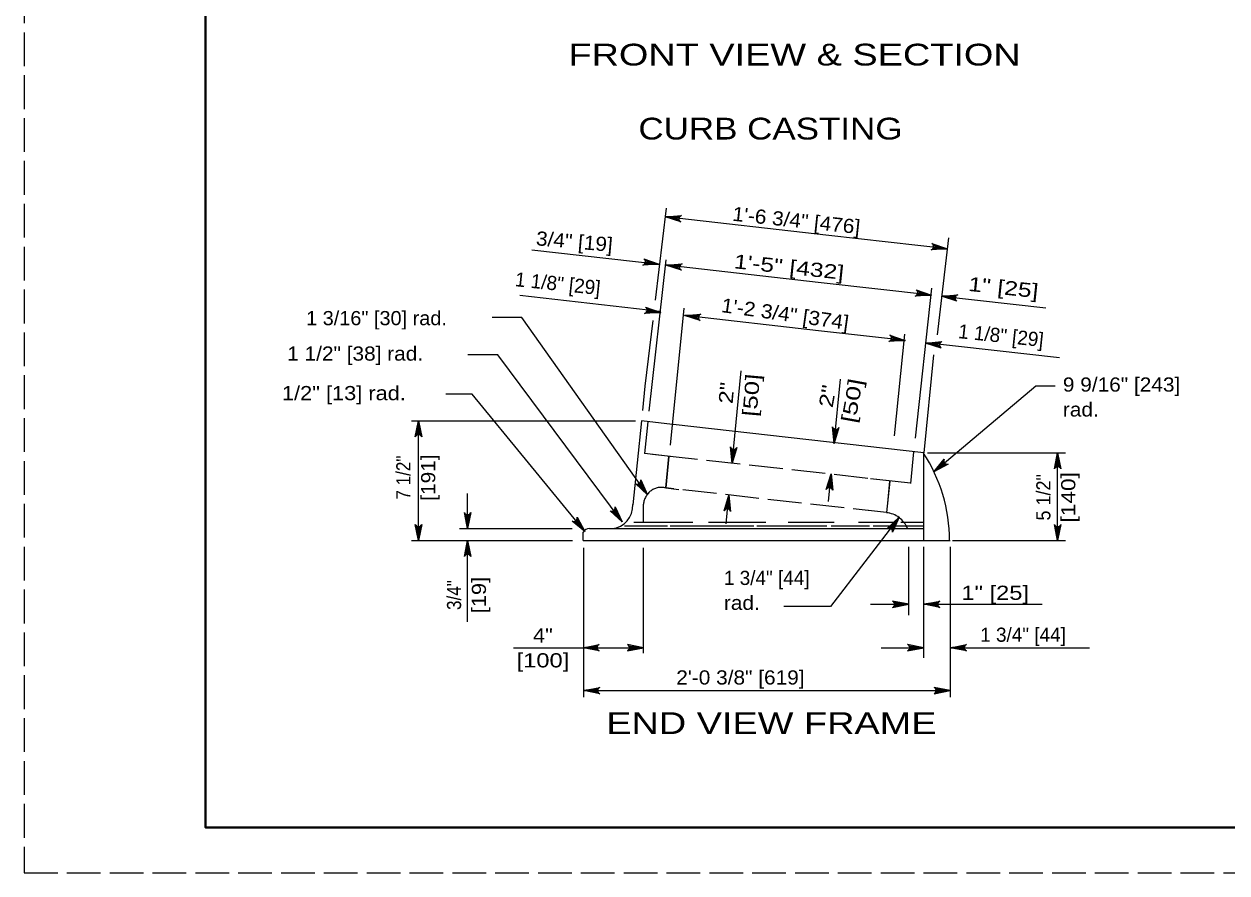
# Model space of a CAD drawing. Extents: x 1352.5 to 1386.5, y 735.9 to 779.9.
# Drawn here: x 1352.51 to 1365.77, y 735.92 to 745.27 of the extents above; entities that cross this region are included whole.
import ezdxf
from ezdxf.enums import TextEntityAlignment as Align

# ---------------------------------------------------------------- set-up
doc = ezdxf.new("R2010")
doc.units = 0
doc.header["$LTSCALE"] = 0.062
doc.linetypes.add('LONG_DASHED', pattern=[7.5, 6, -1.5])
doc.layers.add('1', color=7, linetype='Continuous', lineweight=13)

msp = doc.modelspace()

# ---------------------------------------------------------------- linework, layer by layer
at = {"layer": '1'}
for p, q in [((1359.587, 743.23908), (1359.467, 742.22625)), ((1359.73892, 743.14742), (1359.57708, 743.14308)), ((1361.38233, 742.93892), (1359.57708, 743.14308)), ((1359.72942, 743.12592), (1359.57708, 743.14308)), ((1359.73058, 743.11125), (1359.57708, 743.14308)), ((1359.7355, 743.10025), (1359.57708, 743.14308)), ((1359.73233, 743.13692), (1359.57708, 743.14308)), ((1362.68767, 742.79175), (1361.38233, 742.93908)), ((1362.53067, 742.83942), (1362.68767, 742.79175)), ((1362.53525, 742.82825), (1362.68767, 742.79175)), ((1362.70017, 742.91475), (1362.5735, 741.84375)), ((1359.51, 742.62008), (1358.11, 742.77825)), ((1362.52583, 742.79242), (1362.68767, 742.79175)), ((1362.53275, 742.80275), (1362.68767, 742.79175)), ((1362.536, 742.81358), (1362.68767, 742.79175)), ((1359.35008, 742.62375), (1359.51192, 742.62308)), ((1359.35492, 742.67075), (1359.51192, 742.62308)), ((1359.357, 742.63408), (1359.51192, 742.62308)), ((1359.3595, 742.65958), (1359.51192, 742.62308)), ((1359.36025, 742.64508), (1359.51192, 742.62308)), ((1359.58392, 742.67075), (1359.39925, 741.00425)), ((1359.7465, 742.61608), (1359.58467, 742.61175)), ((1359.73692, 742.59458), (1359.58467, 742.61175)), ((1359.73808, 742.57992), (1359.58467, 742.61175)), ((1359.74308, 742.56892), (1359.58467, 742.61175)), ((1359.73983, 742.60558), (1359.58467, 742.61175)), ((1361.29808, 742.41842), (1359.59208, 742.61092)), ((1362.51208, 742.28125), (1361.29808, 742.41842)), ((1362.51375, 742.36025), (1362.33075, 740.70608)), ((1362.35558, 742.32892), (1362.51258, 742.28125)), ((1362.35767, 742.29208), (1362.51258, 742.28125)), ((1362.36017, 742.31775), (1362.51258, 742.28125)), ((1362.36092, 742.30308), (1362.51258, 742.28125)), ((1359.51967, 742.10225), (1357.97608, 742.27658)), ((1362.35075, 742.28192), (1362.51258, 742.28125)), ((1362.78325, 742.27392), (1362.62142, 742.26958)), ((1362.77367, 742.25242), (1362.62142, 742.26958)), ((1362.77483, 742.23775), (1362.62142, 742.26958)), ((1362.77983, 742.22675), (1362.62142, 742.26958)), ((1362.77658, 742.26342), (1362.62142, 742.26958)), ((1363.77258, 742.13875), (1362.626, 742.26842)), ((1359.36867, 742.09042), (1359.5305, 742.08975)), ((1359.3735, 742.13742), (1359.5305, 742.08975)), ((1359.37558, 742.10058), (1359.5305, 742.08975)), ((1359.37808, 742.12625), (1359.5305, 742.08975)), ((1359.37883, 742.11158), (1359.5305, 742.08975)), ((1359.78258, 742.13742), (1359.63108, 740.63058)), ((1359.95242, 742.06192), (1359.79058, 742.05758)), ((1359.94283, 742.04042), (1359.79058, 742.05758)), ((1359.94408, 742.02575), (1359.79058, 742.05758)), ((1359.949, 742.01475), (1359.79058, 742.05758)), ((1359.94575, 742.05158), (1359.79058, 742.05758)), ((1361.26883, 741.89058), (1359.79617, 742.05708)), ((1359.44067, 742.00342), (1359.35492, 741.27958)), ((1362.22567, 741.78275), (1361.26883, 741.89042)), ((1362.06208, 741.78358), (1362.224, 741.78292)), ((1362.067, 741.83058), (1362.224, 741.78292)), ((1362.06908, 741.79392), (1362.224, 741.78292)), ((1362.07158, 741.81942), (1362.224, 741.78292)), ((1362.07233, 741.80475), (1362.224, 741.78292)), ((1362.2155, 741.85375), (1362.10217, 740.73125)), ((1362.60975, 741.75908), (1362.44792, 741.75492)), ((1362.60025, 741.73775), (1362.44792, 741.75492)), ((1362.60142, 741.72308), (1362.44792, 741.75492)), ((1362.60633, 741.71208), (1362.44792, 741.75492)), ((1362.60317, 741.74875), (1362.44792, 741.75492)), ((1363.92175, 741.59175), (1362.449, 741.75758)), ((1362.53558, 741.62392), (1362.42692, 740.54575)), ((1360.31492, 740.43275), (1360.41575, 741.44808)), ((1359.35492, 741.27958), (1359.32792, 741.01208)), ((1361.44, 740.65325), (1361.50975, 741.35542)), ((1356.78225, 740.89742), (1358.246, 740.89742)), ((1356.835, 740.73525), (1356.85983, 740.89742)), ((1356.84542, 740.74142), (1356.85983, 740.89742)), ((1356.85983, 740.74425), (1356.85983, 740.89742)), ((1356.87117, 740.74258), (1356.85983, 740.89742)), ((1356.88225, 740.73708), (1356.85983, 740.89742)), ((1358.246, 740.89742), (1359.25083, 740.89742)), ((1361.4335, 740.81508), (1361.44, 740.65325)), ((1361.48067, 740.81225), (1361.44, 740.65325)), ((1361.444, 740.80858), (1361.44, 740.65325)), ((1361.46975, 740.80725), (1361.44, 740.65325)), ((1361.45517, 740.80575), (1361.44, 740.65325)), ((1360.30842, 740.59442), (1360.31492, 740.43275)), ((1360.35558, 740.59158), (1360.31492, 740.43275)), ((1360.31892, 740.58792), (1360.31492, 740.43275)), ((1360.34467, 740.58658), (1360.31492, 740.43275)), ((1360.33, 740.58525), (1360.31492, 740.43275)), ((1361.43908, 740.64442), (1361.44, 740.65325)), ((1359.69983, 740.49942), (1359.43742, 740.52808)), ((1359.5845, 740.15875), (1359.61908, 740.50458)), ((1362.46742, 740.54625), (1363.98767, 740.54625)), ((1362.64717, 740.45558), (1362.53908, 740.33508)), ((1362.65017, 740.44358), (1362.53908, 740.33508)), ((1362.65625, 740.43392), (1362.53908, 740.33508)), ((1363.87792, 740.38275), (1363.90275, 740.54492)), ((1363.88833, 740.38892), (1363.90275, 740.54492)), ((1363.90275, 739.58025), (1363.90275, 740.54492)), ((1363.90275, 740.39175), (1363.90275, 740.54492)), ((1363.91408, 740.39008), (1363.90275, 740.54492)), ((1363.92517, 740.38458), (1363.90275, 740.54492)), ((1361.36542, 740.15442), (1361.40617, 740.31325)), ((1361.376, 740.01008), (1361.40617, 740.31325)), ((1361.37633, 740.15942), (1361.40617, 740.31325)), ((1361.39092, 740.16075), (1361.40617, 740.31325)), ((1361.40208, 740.15808), (1361.40617, 740.31325)), ((1361.41258, 740.15158), (1361.40617, 740.31325)), ((1362.66767, 740.42475), (1362.53908, 740.33508)), ((1362.67908, 740.42075), (1362.53908, 740.33508)), ((1359.27125, 740.20075), (1359.38217, 740.08292)), ((1359.28342, 740.20275), (1359.38217, 740.08292)), ((1359.29367, 740.20808), (1359.38217, 740.08292)), ((1359.30375, 740.21858), (1359.38217, 740.08292)), ((1359.30867, 740.22975), (1359.38217, 740.08292)), ((1362.27992, 740.21208), (1361.83983, 740.26008)), ((1362.05142, 740.23342), (1362.02925, 739.99008)), ((1357.4005, 739.71192), (1357.4005, 740.09792)), ((1359.5845, 740.15875), (1359.553, 740.16492)), ((1359.58442, 740.15875), (1359.72808, 740.14292)), ((1360.23908, 739.92125), (1360.27983, 740.08025)), ((1360.24842, 739.76442), (1360.27983, 740.08025)), ((1360.25008, 739.92642), (1360.27983, 740.08025)), ((1360.26467, 739.92775), (1360.27983, 740.08025)), ((1360.27575, 739.92492), (1360.27983, 740.08025)), ((1360.28625, 739.91842), (1360.27983, 740.08025)), ((1359.00292, 739.90425), (1359.10467, 739.78692)), ((1359.013, 739.90975), (1359.10467, 739.78692)), ((1359.02283, 739.92058), (1359.10467, 739.78692)), ((1359.0275, 739.93175), (1359.10467, 739.78692)), ((1362.01808, 739.88792), (1361.81958, 739.90958)), ((1357.37808, 739.87225), (1357.4005, 739.71192)), ((1357.38917, 739.86675), (1357.4005, 739.71192)), ((1357.42533, 739.87408), (1357.4005, 739.71192)), ((1357.41492, 739.86792), (1357.4005, 739.71192)), ((1357.4005, 739.86508), (1357.4005, 739.71192)), ((1358.57225, 739.78875), (1358.69125, 739.67908)), ((1358.58425, 739.79158), (1358.69125, 739.67908)), ((1358.59408, 739.79758), (1358.69125, 739.67908)), ((1358.60342, 739.80875), (1358.69125, 739.67908)), ((1358.60758, 739.82008), (1358.69125, 739.67908)), ((1358.99083, 739.90192), (1359.10467, 739.78692)), ((1359.23175, 739.78192), (1359.88408, 739.78192)), ((1360.05475, 739.78192), (1360.68767, 739.78192)), ((1360.93217, 739.78192), (1361.44083, 739.78192)), ((1361.70875, 739.78192), (1362.10875, 739.78192)), ((1362.01808, 739.88792), (1362.04508, 739.88375)), ((1362.04208, 739.71892), (1362.15492, 739.83808)), ((1362.05417, 739.71792), (1362.15492, 739.83808)), ((1362.06758, 739.71208), (1362.15492, 739.83808)), ((1362.076, 739.70425), (1362.15492, 739.83808)), ((1362.082, 739.69358), (1362.15492, 739.83808)), ((1362.17475, 739.78192), (1362.42692, 739.78192)), ((1356.83742, 739.74042), (1356.85983, 739.58025)), ((1356.8485, 739.73508), (1356.85983, 739.58025)), ((1356.88458, 739.74242), (1356.85983, 739.58025)), ((1356.87425, 739.73625), (1356.85983, 739.58025)), ((1356.85983, 739.73342), (1356.85983, 739.58025)), ((1357.31267, 739.71192), (1358.55458, 739.71192)), ((1358.99283, 739.71192), (1362.42692, 739.71192)), ((1359.13067, 739.74092), (1359.60433, 739.74092)), ((1359.63158, 739.74092), (1360.55558, 739.74092)), ((1360.58675, 739.74092), (1361.35933, 739.74092)), ((1361.406, 739.74092), (1361.82917, 739.74092)), ((1361.868, 739.74092), (1362.42692, 739.74092)), ((1363.88033, 739.74042), (1363.90275, 739.58025)), ((1363.89142, 739.73508), (1363.90275, 739.58025)), ((1363.9275, 739.74242), (1363.90275, 739.58025)), ((1363.91717, 739.73625), (1363.90275, 739.58025)), ((1363.90275, 739.73342), (1363.90275, 739.58025)), ((1356.78225, 739.58025), (1358.55458, 739.58025)), ((1357.37575, 739.41792), (1357.4005, 739.58025)), ((1357.38608, 739.42408), (1357.4005, 739.58025)), ((1357.4005, 738.68292), (1357.4005, 739.58025)), ((1357.4005, 739.42692), (1357.4005, 739.58025)), ((1357.41183, 739.42525), (1357.4005, 739.58025)), ((1357.42292, 739.41992), (1357.4005, 739.58025)), ((1358.55458, 739.58025), (1358.5565, 739.58025)), ((1362.261, 738.75725), (1362.261, 739.51208)), ((1362.42692, 738.28842), (1362.42692, 739.51208)), ((1362.7195, 739.51208), (1362.7195, 737.85392)), ((1362.74392, 739.58025), (1363.98767, 739.58025)), ((1357.4005, 739.35225), (1357.4005, 739.49558)), ((1358.68108, 737.85392), (1358.68108, 739.50058)), ((1359.33825, 738.33992), (1359.33825, 739.50058)), ((1361.84217, 738.87742), (1362.261, 738.87742)), ((1362.09883, 738.85258), (1362.261, 738.87742)), ((1362.10075, 738.89975), (1362.261, 738.87742)), ((1362.105, 738.86292), (1362.261, 738.87742)), ((1362.10617, 738.88875), (1362.261, 738.87742)), ((1362.10783, 738.87742), (1362.261, 738.87742)), ((1362.58725, 738.89975), (1362.42692, 738.87742)), ((1362.58183, 738.88875), (1362.42692, 738.87742)), ((1362.42692, 738.87742), (1363.73158, 738.87742)), ((1362.58017, 738.87742), (1362.42692, 738.87742)), ((1362.583, 738.86292), (1362.42692, 738.87742)), ((1362.58908, 738.85258), (1362.42692, 738.87742)), ((1357.90625, 738.39975), (1359.33825, 738.39975)), ((1358.83383, 738.42208), (1358.6735, 738.39975)), ((1358.82833, 738.41108), (1358.6735, 738.39975)), ((1358.82675, 738.39975), (1358.6735, 738.39975)), ((1358.82958, 738.38525), (1358.6735, 738.39975)), ((1358.83567, 738.37492), (1358.6735, 738.39975)), ((1359.176, 738.37492), (1359.33825, 738.39975)), ((1359.17792, 738.42208), (1359.33825, 738.39975)), ((1359.18217, 738.38525), (1359.33825, 738.39975)), ((1359.18333, 738.41108), (1359.33825, 738.39975)), ((1359.185, 738.39975), (1359.33825, 738.39975)), ((1361.95858, 738.39975), (1362.42692, 738.39975)), ((1362.02558, 738.39975), (1362.4245, 738.39975)), ((1362.26475, 738.37492), (1362.42692, 738.39975)), ((1362.26658, 738.42208), (1362.42692, 738.39975)), ((1362.27083, 738.38525), (1362.42692, 738.39975)), ((1362.272, 738.41108), (1362.42692, 738.39975)), ((1362.27367, 738.39975), (1362.42692, 738.39975)), ((1362.87983, 738.42208), (1362.7195, 738.39975)), ((1362.87433, 738.41108), (1362.7195, 738.39975)), ((1362.7195, 738.39975), (1364.25225, 738.39975)), ((1362.87275, 738.39975), (1362.7195, 738.39975)), ((1362.87558, 738.38525), (1362.7195, 738.39975)), ((1362.88167, 738.37492), (1362.7195, 738.39975)), ((1358.84133, 737.94992), (1358.68108, 737.92742)), ((1358.83592, 737.93875), (1358.68108, 737.92742)), ((1358.68108, 737.92742), (1362.71725, 737.92742)), ((1358.83425, 737.92742), (1358.68108, 737.92742)), ((1358.83708, 737.91308), (1358.68108, 737.92742)), ((1358.84325, 737.90275), (1358.68108, 737.92742)), ((1362.555, 737.90275), (1362.71725, 737.92742)), ((1362.55692, 737.94992), (1362.71725, 737.92742)), ((1362.56117, 737.91308), (1362.71725, 737.92742)), ((1362.56233, 737.93875), (1362.71725, 737.92742)), ((1362.564, 737.92742), (1362.71725, 737.92742))]:
    msp.add_line(p, q, dxfattribs=at)
at = {"layer": '1', "lineweight": 25}
for p, q in [((1359.31633, 740.89742), (1359.22308, 739.97358)), ((1359.65842, 740.85875), (1359.31633, 740.89742)), ((1362.42692, 740.54625), (1359.66583, 740.85792)), ((1362.42692, 739.58025), (1362.42692, 740.54625)), ((1358.6735, 739.58025), (1358.6735, 739.67225)), ((1358.74383, 739.71192), (1358.99283, 739.71192)), ((1358.6735, 739.58025), (1362.71725, 739.58025))]:
    msp.add_line(p, q, dxfattribs=at)
at = {"layer": '1', "linetype": 'LONG_DASHED'}
for p, q in [((1359.38633, 740.88758), (1359.3515, 740.53808)), ((1359.69983, 740.49942), (1359.3515, 740.53808)), ((1359.61892, 740.50508), (1359.58442, 740.15875)), ((1361.34225, 740.31642), (1359.69983, 740.49925)), ((1362.31442, 740.55825), (1362.27958, 740.20875)), ((1362.27992, 740.21208), (1361.34225, 740.31658)), ((1362.05258, 740.23525), (1362.018, 739.88792)), ((1362.018, 739.88792), (1359.58442, 740.15875)), ((1359.33825, 739.77708), (1359.33825, 739.97875))]:
    msp.add_line(p, q, dxfattribs=at)
msp.add_lwpolyline([(1352.513, 735.91967), (1386.513, 735.91967), (1386.513, 757.91967), (1352.513, 757.91967)], close=True, dxfattribs=at)
at = {"layer": '1', "lineweight": 25}
msp.add_lwpolyline([(1386.013, 736.41967), (1354.513, 736.41967), (1354.513, 757.41967)], dxfattribs=at)
at = {"layer": '1', "lineweight": 40}
msp.add_lwpolyline([(1354.513, 757.41967), (1386.013, 757.41967), (1386.013, 736.41967), (1354.513, 736.41967)], close=True, dxfattribs=at)
msp.add_lwpolyline([(1354.513, 757.41967), (1386.013, 757.41967), (1386.013, 736.41967), (1354.513, 736.41967)], close=True, dxfattribs=at)
at = {"layer": '1'}
for points in [[(1359.74908, 743.08792), (1359.57708, 743.14308), (1359.75708, 743.15842)], [(1362.5175, 742.85208), (1362.68767, 742.79175), (1362.50742, 742.78208)], [(1359.34175, 742.68342), (1359.51192, 742.62308), (1359.33167, 742.61342)], [(1359.75667, 742.55675), (1359.58467, 742.61175), (1359.76458, 742.62708)], [(1362.34242, 742.34158), (1362.51258, 742.28125), (1362.33225, 742.27142)], [(1362.79342, 742.21458), (1362.62142, 742.26958), (1362.80133, 742.28492)], [(1359.38217, 740.08292), (1357.99917, 742.03575), (1357.67083, 742.03575)], [(1359.36033, 742.15008), (1359.5305, 742.08975), (1359.35017, 742.07992)], [(1359.96258, 742.00258), (1359.79058, 742.05758), (1359.9705, 742.07292)], [(1362.05375, 741.84325), (1362.224, 741.78292), (1362.04367, 741.77325)], [(1362.61992, 741.69975), (1362.44792, 741.75492), (1362.62792, 741.77025)], [(1359.10467, 739.78692), (1357.73325, 741.62508), (1357.40492, 741.62508)], [(1362.53908, 740.33508), (1363.664, 741.28342), (1363.87433, 741.28342)], [(1358.69125, 739.67908), (1357.45175, 741.19042), (1357.15908, 741.19042)], [(1356.82442, 740.72042), (1356.85983, 740.89742), (1356.89525, 740.72042)], [(1356.85983, 739.58025), (1356.85983, 739.89758), (1356.85983, 740.89742)], [(1361.49275, 740.82608), (1361.44, 740.65325), (1361.42225, 740.83308)], [(1360.36767, 740.60542), (1360.31492, 740.43275), (1360.29717, 740.61242)], [(1362.69733, 740.42208), (1362.53908, 740.33508), (1362.65167, 740.47625)], [(1363.86733, 740.36792), (1363.90275, 740.54492), (1363.93817, 740.36792)], [(1361.35333, 740.14058), (1361.40617, 740.31325), (1361.42383, 740.13358)], [(1359.30875, 740.24792), (1359.38217, 740.08292), (1359.25092, 740.20708)], [(1360.22708, 739.90758), (1360.27983, 740.08025), (1360.29758, 739.90042)], [(1359.02717, 739.95008), (1359.10467, 739.78692), (1358.97042, 739.90758)], [(1357.43592, 739.88892), (1357.4005, 739.71192), (1357.36508, 739.88892)], [(1358.60633, 739.83842), (1358.69125, 739.67908), (1358.55158, 739.79342)], [(1362.15492, 739.83808), (1361.39892, 738.85458), (1360.88675, 738.85458)], [(1362.02492, 739.71275), (1362.15492, 739.83808), (1362.08308, 739.67242)], [(1356.89525, 739.75725), (1356.85983, 739.58025), (1356.82442, 739.75725)], [(1363.93817, 739.75725), (1363.90275, 739.58025), (1363.86733, 739.75725)], [(1357.36508, 739.40308), (1357.4005, 739.58025), (1357.43592, 739.40308)], [(1362.08392, 738.84192), (1362.261, 738.87742), (1362.08392, 738.91275)], [(1362.604, 738.84192), (1362.42692, 738.87742), (1362.604, 738.91275)], [(1358.85058, 738.36425), (1358.6735, 738.39975), (1358.85058, 738.43508)], [(1359.16117, 738.36425), (1359.33825, 738.39975), (1359.16117, 738.43508)], [(1362.24983, 738.36425), (1362.42692, 738.39975), (1362.24983, 738.43508)], [(1362.89658, 738.36425), (1362.7195, 738.39975), (1362.89658, 738.43508)], [(1358.85817, 737.89208), (1358.68108, 737.92742), (1358.85817, 737.96292)], [(1362.54017, 737.89208), (1362.71725, 737.92742), (1362.54017, 737.96292)]]:
    msp.add_lwpolyline(points, dxfattribs=at)
for centre, start, end in [((1359.7673, 743.12161), 105.64469, 241.47082), ((1362.49827, 742.81906), 283.8788, 59.70493), ((1359.32252, 742.65042), 283.8788, 59.70493), ((1359.77484, 742.5903), 105.64469, 241.47082), ((1362.32316, 742.30848), 283.8788, 59.70493), ((1362.81157, 742.24817), 105.64469, 241.47082), ((1359.34108, 742.11701), 283.8788, 59.70493), ((1359.98078, 742.0362), 105.64469, 241.47082), ((1362.03457, 741.81024), 283.8788, 59.70493), ((1362.63813, 741.73342), 105.64469, 241.47082), ((1361.45888, 740.84376), 196.41236, 332.23849), ((1356.85987, 740.70608), 22.08782, 157.91395), ((1360.33377, 740.62315), 196.41236, 332.23849), ((1362.68539, 740.45848), 152.21645, 288.04257), ((1363.90278, 740.35354), 22.08782, 157.91395), ((1359.27155, 740.23913), 237.39526, 13.22139), ((1361.38721, 740.12285), 16.39591, 152.22204), ((1358.99018, 739.94027), 238.8138, 14.63993), ((1360.26093, 739.88978), 16.39591, 152.22204), ((1357.40046, 739.90326), 202.08782, 337.91395), ((1358.56988, 739.82698), 241.44603, 17.27216), ((1356.85979, 739.77155), 202.08782, 337.91395), ((1362.04589, 739.68075), 347.34147, 123.16759), ((1363.9027, 739.77155), 202.08782, 337.91395), ((1357.40054, 739.3888), 22.08782, 157.91395), ((1362.06965, 738.87743), 292.08605, 67.91218), ((1362.61829, 738.87743), 112.08782, 247.91395), ((1358.86486, 738.39971), 112.08782, 247.91395), ((1359.14686, 738.39971), 292.08605, 67.91218), ((1362.23554, 738.39971), 292.08605, 67.91218), ((1362.91086, 738.39971), 112.08782, 247.91395), ((1358.87244, 737.92751), 112.08782, 247.91395), ((1362.52586, 737.92751), 292.08605, 67.91218)]:
    msp.add_arc(centre, 0.03822, start, end, dxfattribs=at)
at = {"layer": '1', "lineweight": 25}
for centre, major_axis, start_param, end_param in [((1361.12412, 739.58087), (0, 1.67953), 4.71197243, 5.32302093), ((1358.97426, 739.9736), (0, 0.26346), 3.21600171, 4.73074757), ((1358.74383, 739.62408), (0, 0.08782), 6.28318531, 7.27309131)]:
    msp.add_ellipse(centre, major_axis=major_axis, ratio=0.944544, start_param=start_param, end_param=end_param, dxfattribs=at)
at = {"layer": '1', "linetype": 'LONG_DASHED'}
for centre, major_axis, start_param, end_param in [((1359.53416, 739.95709), (0, 0.20857), 6.02499521, 7.74990702), ((1361.98629, 739.58245), (0, 0.30737), 5.14953248, 6.17354038)]:
    msp.add_ellipse(centre, major_axis=major_axis, ratio=0.944544, start_param=start_param, end_param=end_param, dxfattribs=at)

# ---------------------------------------------------------------- texts
at = {"layer": '1'}
for s, height, width, p in [('FRONT VIEW & SECTION', 0.24, 1.3, (1358.51183, 744.811)), ('1 3/16" [30] rad.', 0.156, 1.05, (1355.62117, 741.95125)), ('1 1/2" [38] rad.', 0.156, 1.1, (1355.41283, 741.56075)), ('9 9/16" [243]', 0.156, 1.1, (1363.96033, 741.21975)), ('1/2" [13] rad.', 0.156, 1.15, (1355.35458, 741.12558)), ('rad.', 0.156, 1.1, (1363.96033, 740.94558)), ('rad.', 0.156, 1.1, (1360.22492, 738.81642)), ('1" [25]', 0.156, 1.25, (1362.84208, 738.92675)), ('2\'-0 3/8" [619]', 0.156, 1.1, (1359.7, 737.99442)), ('END VIEW FRAME', 0.24, 1.3, (1358.9285, 737.44925))]:
    msp.add_text(s, height=height, dxfattribs=dict(at, width=width)).set_placement(p)
for s, height, width, p in [('CURB CASTING', 0.24, 1.2, (1360.73775, 743.996)), ('4"', 0.156, 1.15, (1358.23058, 738.45692)), ('[100]', 0.156, 1.25, (1358.23058, 738.18292))]:
    msp.add_text(s, height=height, dxfattribs=dict(at, width=width)).set_placement(p, align=Align.CENTER)
for s, rotation, width, p in [('1\'-6 3/4" [476]', 354, 1.1, (1360.31258, 743.10225)), ('3/4" [19]', 355.004, 1.1, (1358.14942, 742.83208)), ('1\'-5" [432]', 354, 1.3, (1360.32867, 742.57908)), ('1" [25]', 354, 1.3, (1362.91183, 742.32975)), ('1\'-2 3/4" [374]', 352, 1.1, (1360.18967, 742.09642))]:
    msp.add_text(s, height=0.156, rotation=rotation, dxfattribs=dict(at, width=width)).set_placement(p)
for p in [(1357.91733, 742.38142), (1362.801, 741.80958)]:
    msp.add_text('1 1/8" [29]', height=0.156, rotation=354, dxfattribs=at).set_placement(p)
for s, rotation, width, p in [('[50]', 84.959, 1.35, (1360.6041, 741.17415)), ('2"', 84.959, 1.25, (1360.33106, 741.19827)), ('2"', 79.778, 1.3, (1361.44361, 741.15574)), ('[50]', 79.778, 1.4, (1361.71338, 741.10712)), ('7 1/2"', 90, 0.9, (1356.77, 740.27304)), ('[191]', 90, 1.1, (1357.04408, 740.27304)), ('5 1/2"', 90, 0.95, (1363.82333, 740.05567)), ('[140]', 90, 1.2, (1364.09742, 740.05558)), ('3/4"', 90, 0.9, (1357.32917, 738.97925)), ('[19]', 90, 1.15, (1357.60325, 738.97921))]:
    msp.add_text(s, height=0.156, rotation=rotation, dxfattribs=dict(at, width=width)).set_placement(p, align=Align.CENTER)
for p in [(1360.22492, 739.09058), (1363.04942, 738.46492)]:
    msp.add_text('1 3/4" [44]', height=0.156, dxfattribs=at).set_placement(p)

doc.saveas('drawing.dxf')
